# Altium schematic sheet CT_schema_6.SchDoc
size 529 x 503 mm
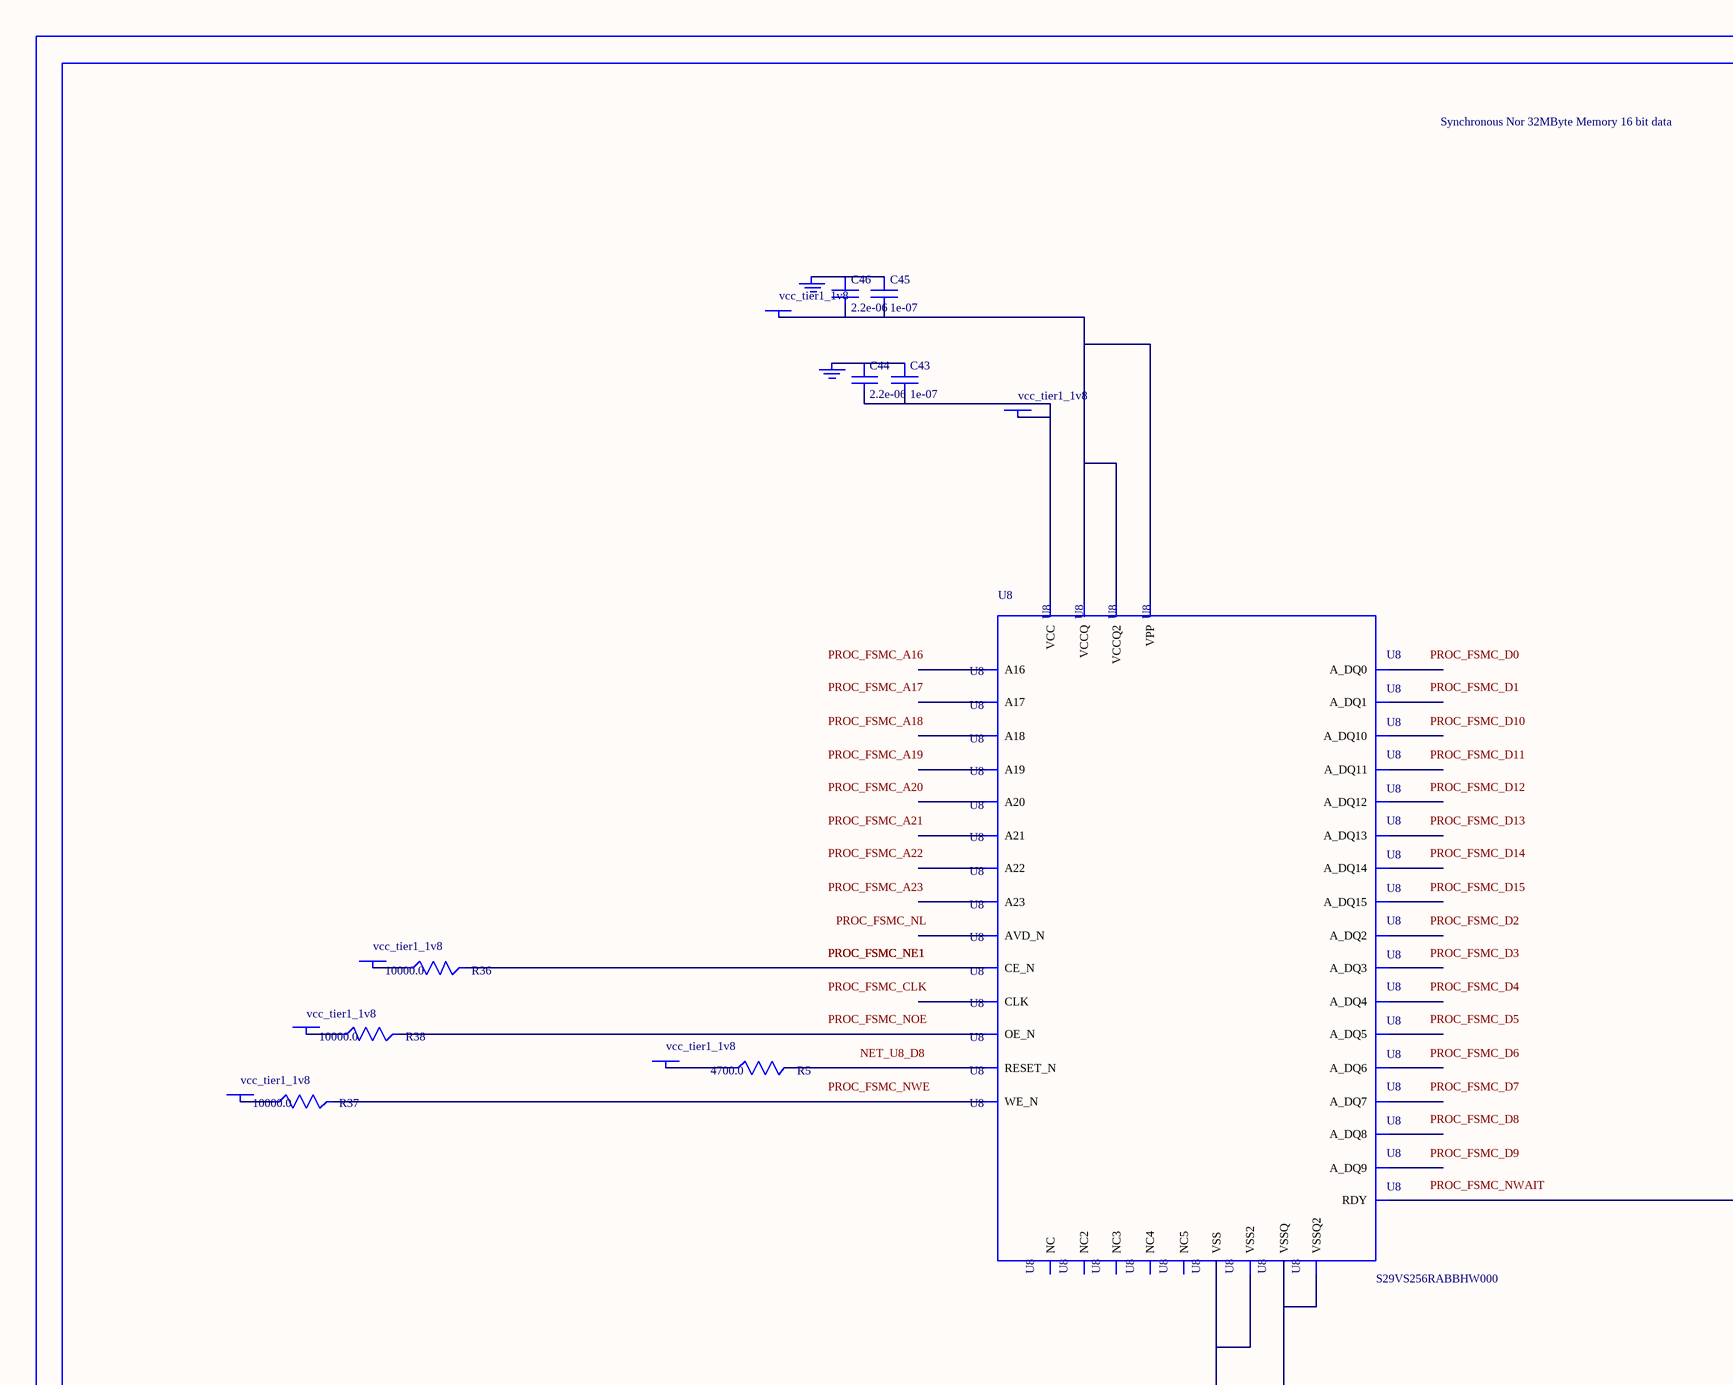
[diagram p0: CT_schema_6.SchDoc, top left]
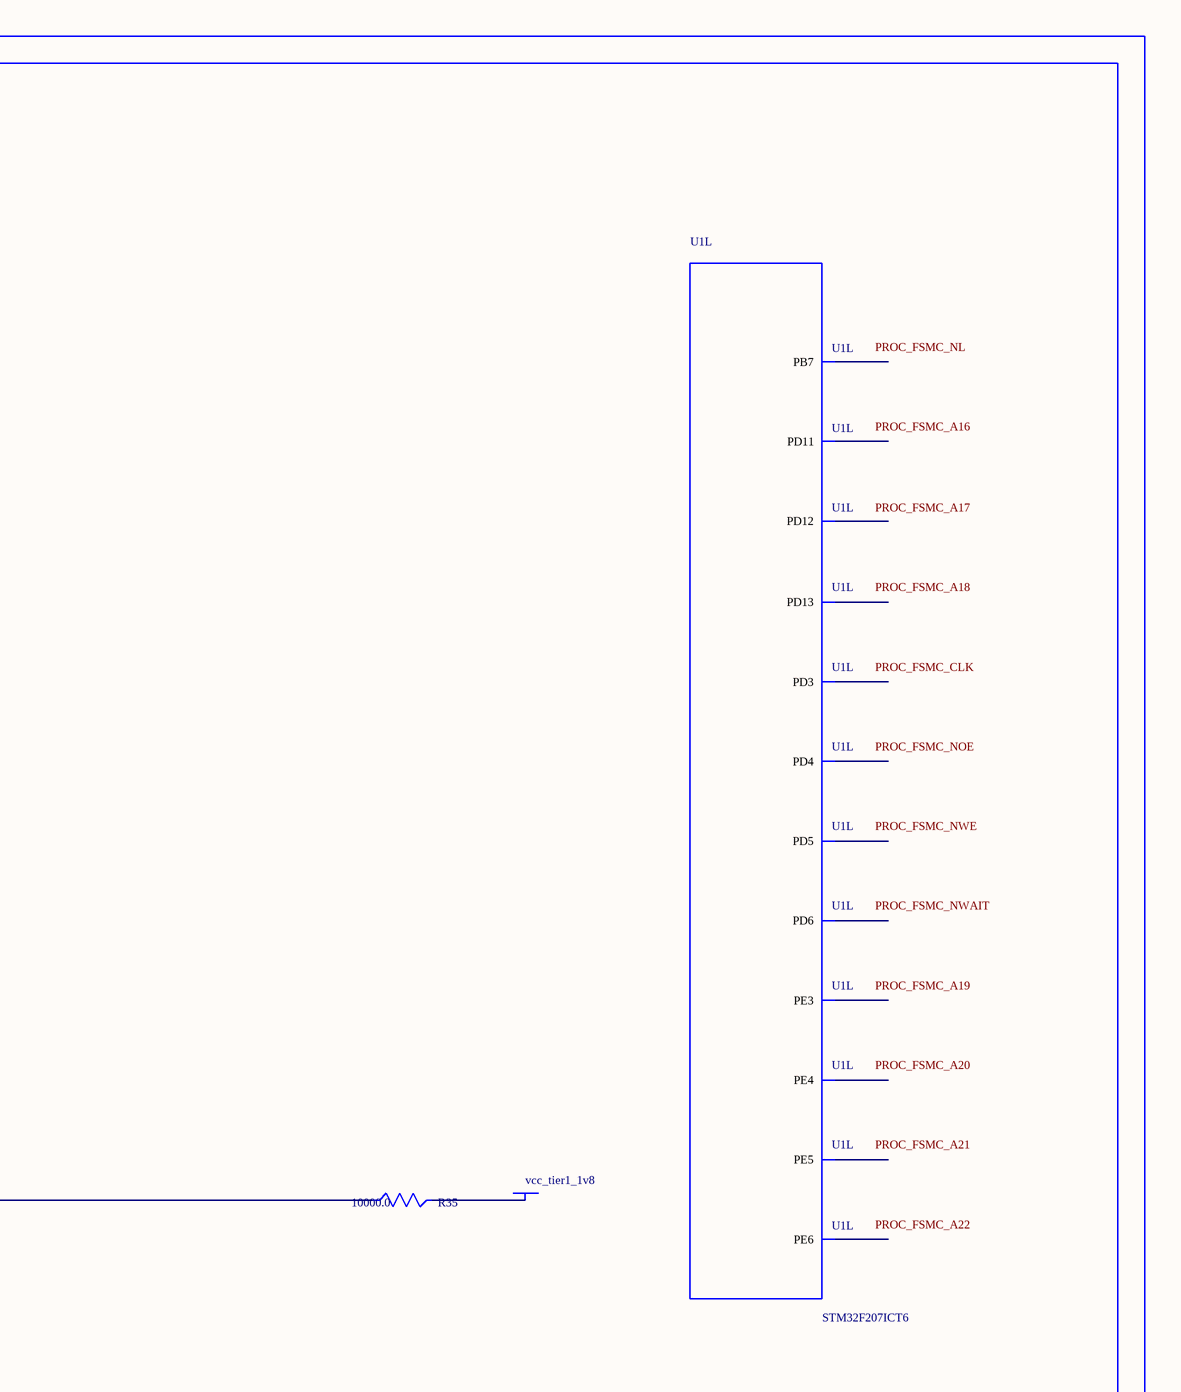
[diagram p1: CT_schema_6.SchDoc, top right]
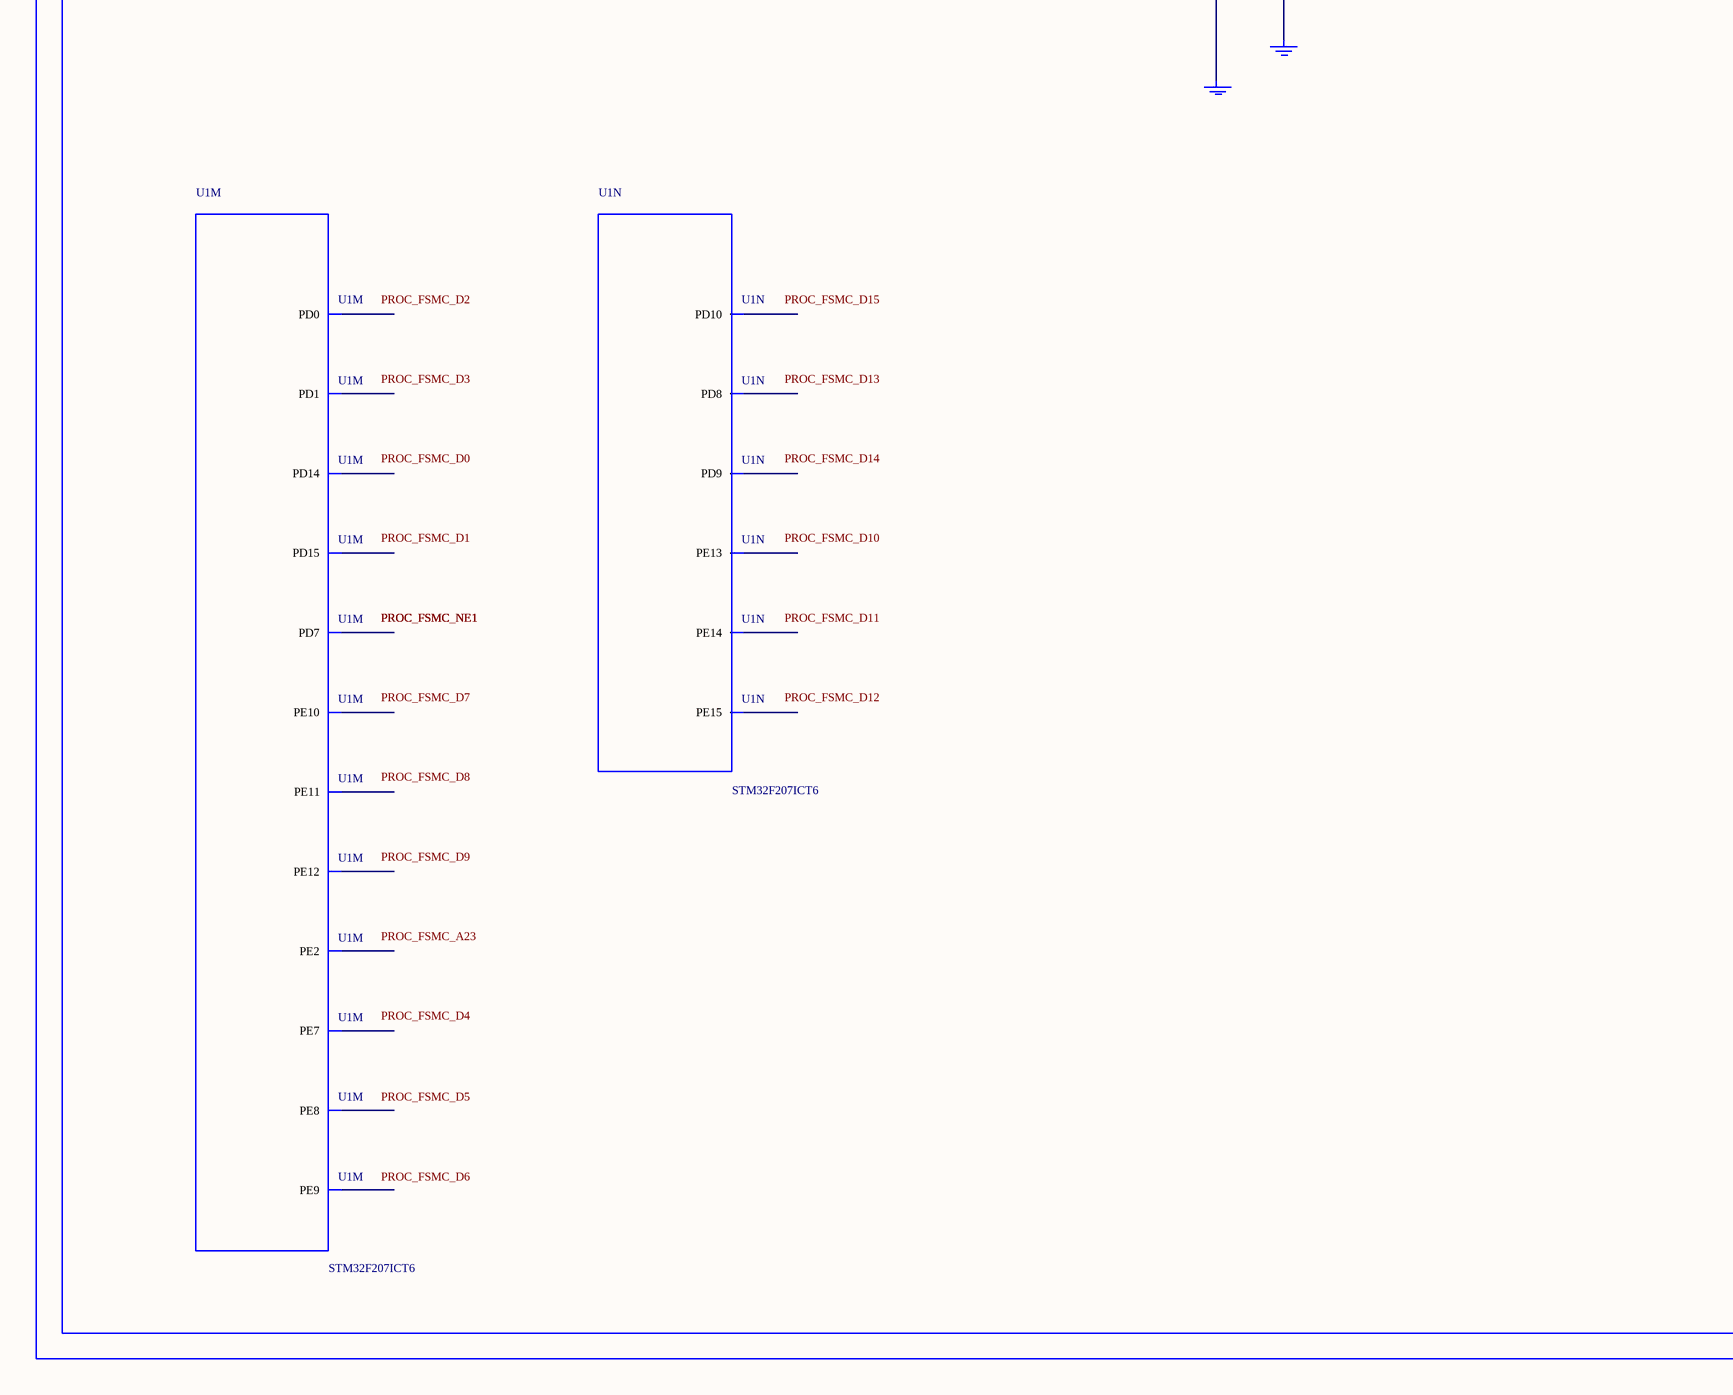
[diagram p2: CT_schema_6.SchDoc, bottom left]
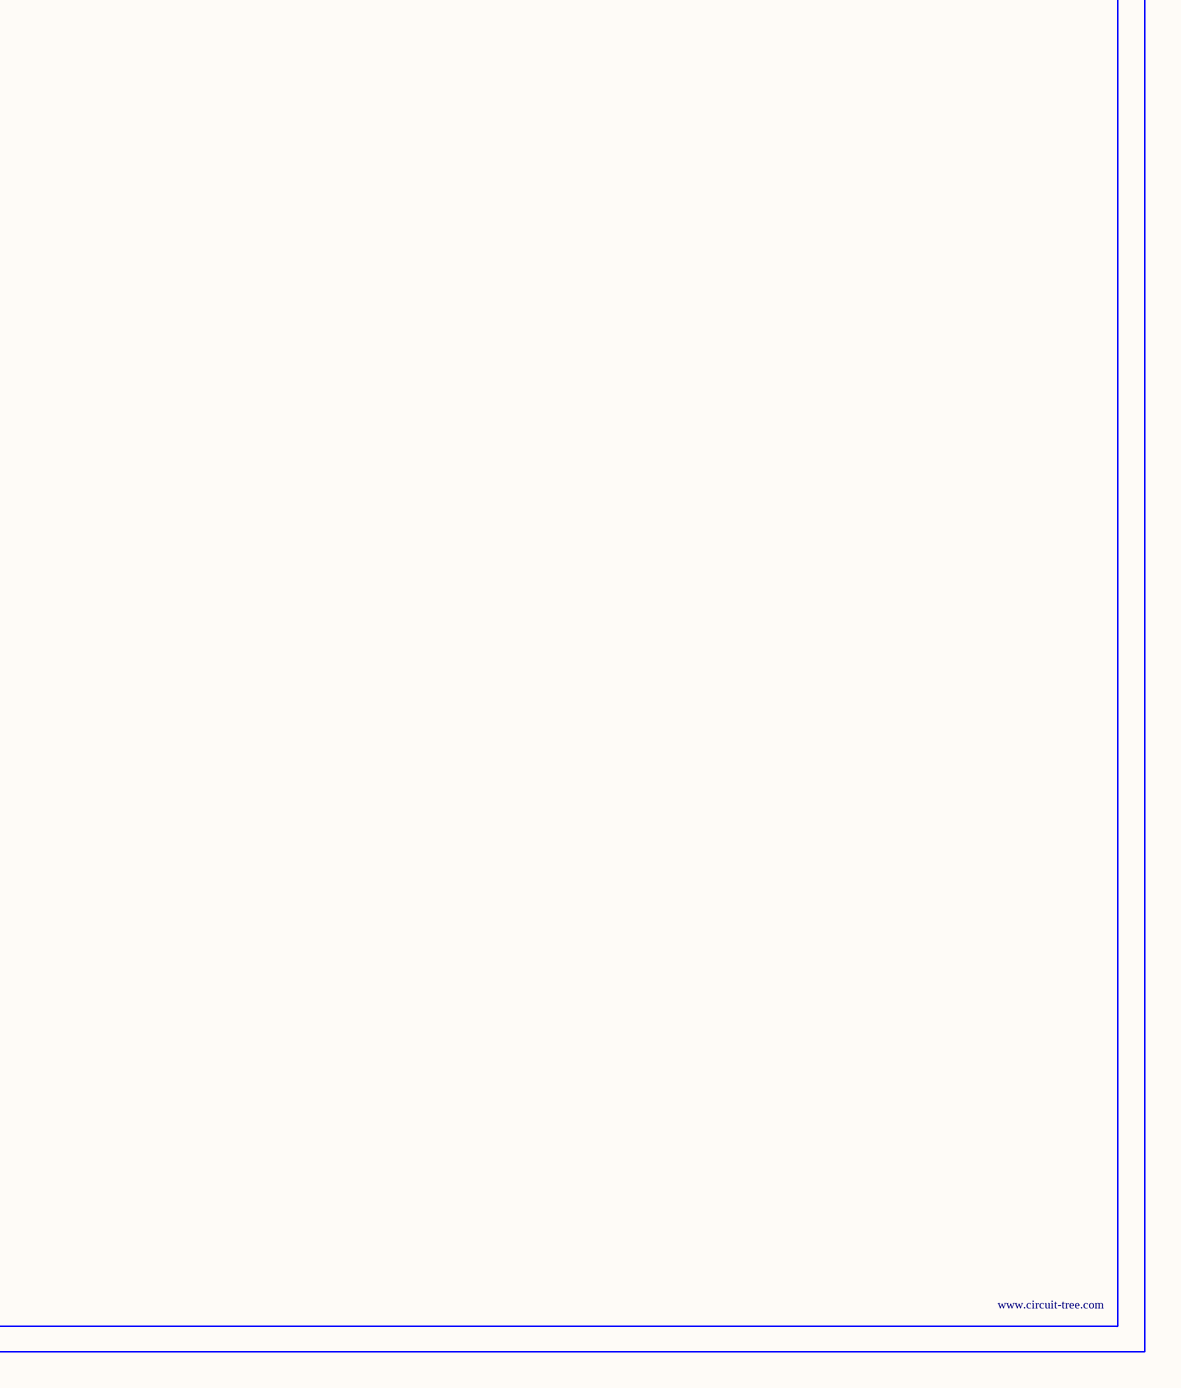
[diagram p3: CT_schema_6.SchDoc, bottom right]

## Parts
BORDER5  (no value)
C43  1e-07  [C0402]
C44  2.2e-06  [C0603]
C45  1e-07  [C0402]
C46  2.2e-06  [C0603]
GND_INSTANCE_5_0  (no value)
GND_INSTANCE_5_1  (no value)
GND_INSTANCE_5_2  (no value)
GND_INSTANCE_5_3  (no value)
POWER_INSTANCE_5_0  vcc_tier1_1v8
POWER_INSTANCE_5_1  vcc_tier1_1v8
POWER_INSTANCE_5_2  vcc_tier1_1v8
POWER_INSTANCE_5_3  vcc_tier1_1v8
POWER_INSTANCE_5_4  vcc_tier1_1v8
POWER_INSTANCE_5_5  vcc_tier1_1v8
POWER_INSTANCE_5_6  vcc_tier1_1v8
R5  4700.0  [R0603]
R35  10000.0  [R0603]
R36  10000.0  [R0603]
R37  10000.0  [R0603]
R38  10000.0  [R0603]
U1  STM32F207ICT6  [LQFP176]  (parts L,M,N of 14)
U8  S29VS256RABBHW000  [S29VS256RABBHW000]

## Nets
NetC43_1: C43.1 C44.1 GND_INSTANCE_5_0.0(GND)
NetC43_2: C43.2 C44.2 POWER_INSTANCE_5_0.0(PWR) U8.C7(VCC)
NetC45_1: C45.1 C46.1 GND_INSTANCE_5_1.0(GND)
NetC45_2: C45.2 C46.2 POWER_INSTANCE_5_1.0(PWR) U8.C9(VPP) U8.D3(VCCQ) U8.F10(VCCQ2)
NetGND_INSTANCE_5_2_0: GND_INSTANCE_5_2.0(GND) U8.C5(VSS) U8.D12(VSS2)
NetGND_INSTANCE_5_3_0: GND_INSTANCE_5_3.0(GND) U8.E3(VSSQ) U8.F5(VSSQ2)
NetPOWER_INSTANCE_5_2_0: POWER_INSTANCE_5_2.0(PWR) R35.2
NetPOWER_INSTANCE_5_3_0: POWER_INSTANCE_5_3.0(PWR) R36.1
NetPOWER_INSTANCE_5_4_0: POWER_INSTANCE_5_4.0(PWR) R37.1
NetPOWER_INSTANCE_5_5_0: POWER_INSTANCE_5_5.0(PWR) R38.1
NetPOWER_INSTANCE_5_6_0: POWER_INSTANCE_5_6.0(PWR) R5.1
NetR5_2: R5.2 U8.D8(RESET_N)
NetR35_1: R35.1 U8.C3(RDY)
NetR36_2: R36.2 U8.D11(CE_N)
NetR37_2: R37.2 U8.C8(WE_N)
NetR38_2: R38.2 U8.E12(OE_N)

Not connected (* = marked no-connect by the designer): U1 1(PE2) 2(PE3) 3(PE4) 4(PE5) 5(PE6) 68(PE7) 69(PE8) 70(PE9) 73(PE10) 74(PE11) 75(PE12) 76(PE13) 77(PE14) 78(PE15) 96(PD8) 97(PD9) 98(PD10) 99(PD11) 100(PD12) 101(PD13) 104(PD14) 105(PD15) 142(PD0) 143(PD1) 145(PD3) 146(PD4) 147(PD5) 150(PD6) 151(PD7) 165(PB7); U8 A1(NC) A14(NC2) C4(A21) C6(CLK) C10(A19) C11(A17) C12(A22) D4(A16) D5(A20) D6(AVD_N) D7(A23) D9(NC3) D10(A18) E4(A_DQ8) E5(A_DQ9) E6(A_DQ2) E7(A_DQ3) E8(A_DQ12) E9(A_DQ13) E10(A_DQ6) E11(A_DQ7) F3(A_DQ0) F4(A_DQ1) F6(A_DQ10) F7(A_DQ11) F8(A_DQ4) F9(A_DQ5) F11(A_DQ14) F12(A_DQ15) H1(NC4) H14(NC5)

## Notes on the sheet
- Labels drawn without touching a wire or pin: NET_U8_D8, PROC_FSMC_A16, PROC_FSMC_A17, PROC_FSMC_A18, PROC_FSMC_A19, PROC_FSMC_A20, PROC_FSMC_A21, PROC_FSMC_A22, PROC_FSMC_A23, PROC_FSMC_CLK, PROC_FSMC_D0, PROC_FSMC_D1, PROC_FSMC_D2, PROC_FSMC_D3, PROC_FSMC_D4, PROC_FSMC_D5, PROC_FSMC_D6, PROC_FSMC_D7, PROC_FSMC_D8, PROC_FSMC_D9, PROC_FSMC_D10, PROC_FSMC_D11, PROC_FSMC_D12, PROC_FSMC_D13, PROC_FSMC_D14, PROC_FSMC_D15, PROC_FSMC_NL, PROC_FSMC_NOE, PROC_FSMC_NWAIT, PROC_FSMC_NWE

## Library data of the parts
BORDER5 = BORDER_PAGE5
C43 C45 = C0402C104K3RACTU
C44 C46 = C0603C225K8RACTU
GND_INSTANCE_5_0-GND_INSTANCE_5_3 = GND
POWER_INSTANCE_5_0-POWER_INSTANCE_5_6 = PWR
R5 = RC0603JR-074K7L
R35-R38 = RC0603JR-0710KL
